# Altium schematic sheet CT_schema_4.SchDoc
size 283 x 147 mm
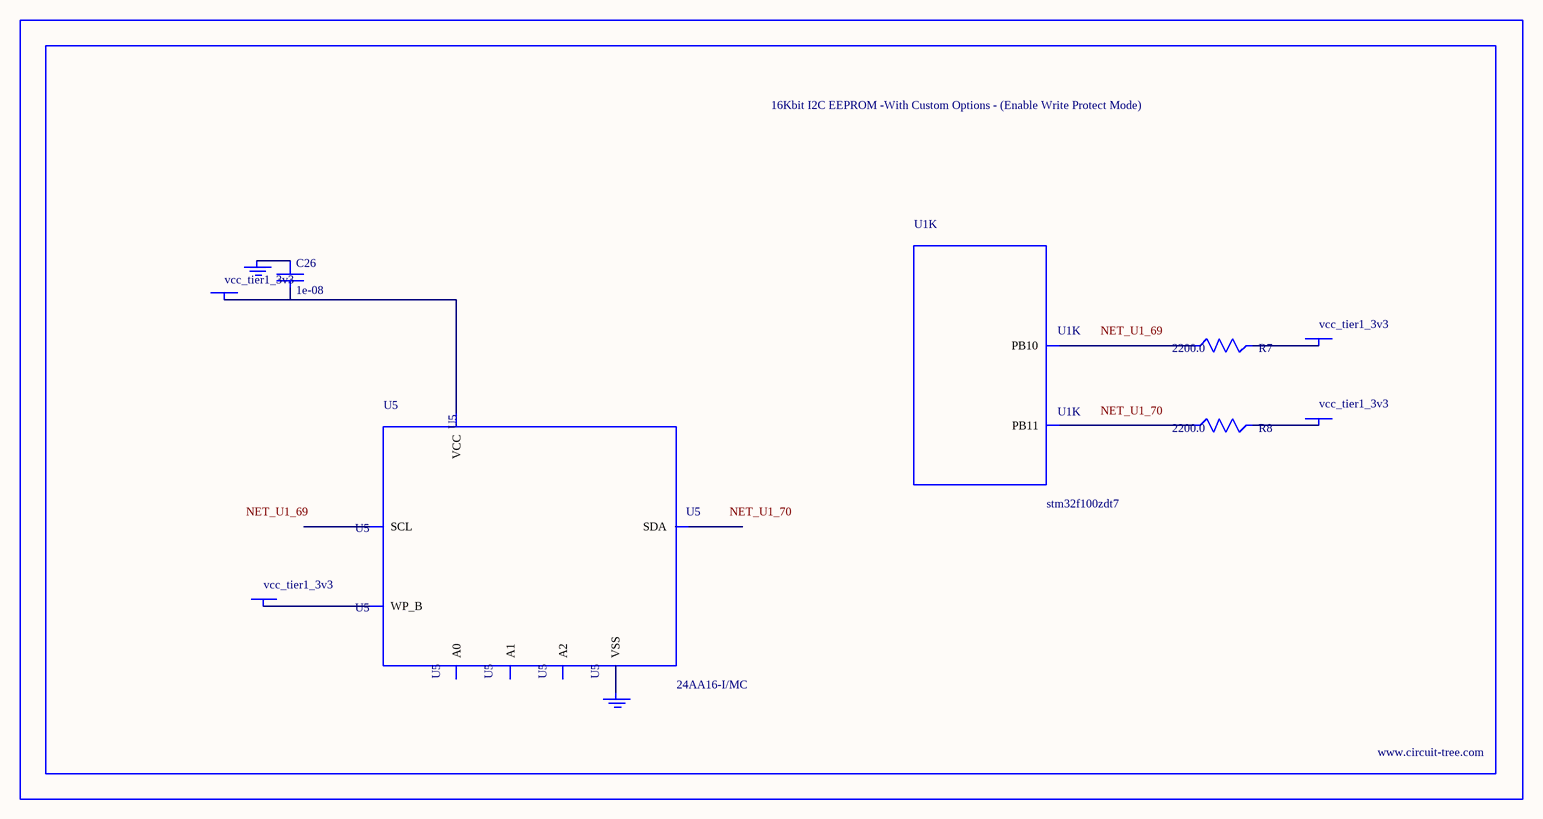
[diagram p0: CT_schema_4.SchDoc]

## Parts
BORDER3  (no value)
C26  1e-08  [C0402]
GND_INSTANCE_3_0  (no value)
GND_INSTANCE_3_1  (no value)
POWER_INSTANCE_3_0  vcc_tier1_3v3
POWER_INSTANCE_3_1  vcc_tier1_3v3
POWER_INSTANCE_3_2  vcc_tier1_3v3
POWER_INSTANCE_3_3  vcc_tier1_3v3
R7  2200.0  [R0603]
R8  2200.0  [R0603]
U1  stm32f100zdt7  [LQFP144]  (part K of 12)
U5  24AA16-I/MC  [TDFN-8/6MM]

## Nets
NetC26_1: C26.1 GND_INSTANCE_3_0.0(GND)
NetC26_2: C26.2 POWER_INSTANCE_3_1.0(PWR) U5.8(VCC)
NetGND_INSTANCE_3_1_0: GND_INSTANCE_3_1.0(GND) U5.4(VSS)
NetPOWER_INSTANCE_3_0_0: POWER_INSTANCE_3_0.0(PWR) U5.7(WP_B)
NetPOWER_INSTANCE_3_2_0: POWER_INSTANCE_3_2.0(PWR) R7.2
NetPOWER_INSTANCE_3_3_0: POWER_INSTANCE_3_3.0(PWR) R8.2
NetR7_1: R7.1 U1.69(PB10)
NetR8_1: R8.1 U1.70(PB11)

Not connected (* = marked no-connect by the designer): U5 1(A0) 2(A1) 3(A2) 5(SDA) 6(SCL)

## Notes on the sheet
- Labels drawn without touching a wire or pin: NET_U1_69, NET_U1_70

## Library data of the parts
BORDER3 = BORDER_PAGE3
C26 = C0402C103K3RAC
GND_INSTANCE_3_0 GND_INSTANCE_3_1 = GND
POWER_INSTANCE_3_0-POWER_INSTANCE_3_3 = PWR
R7 R8 = RC0603JR-072K2L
